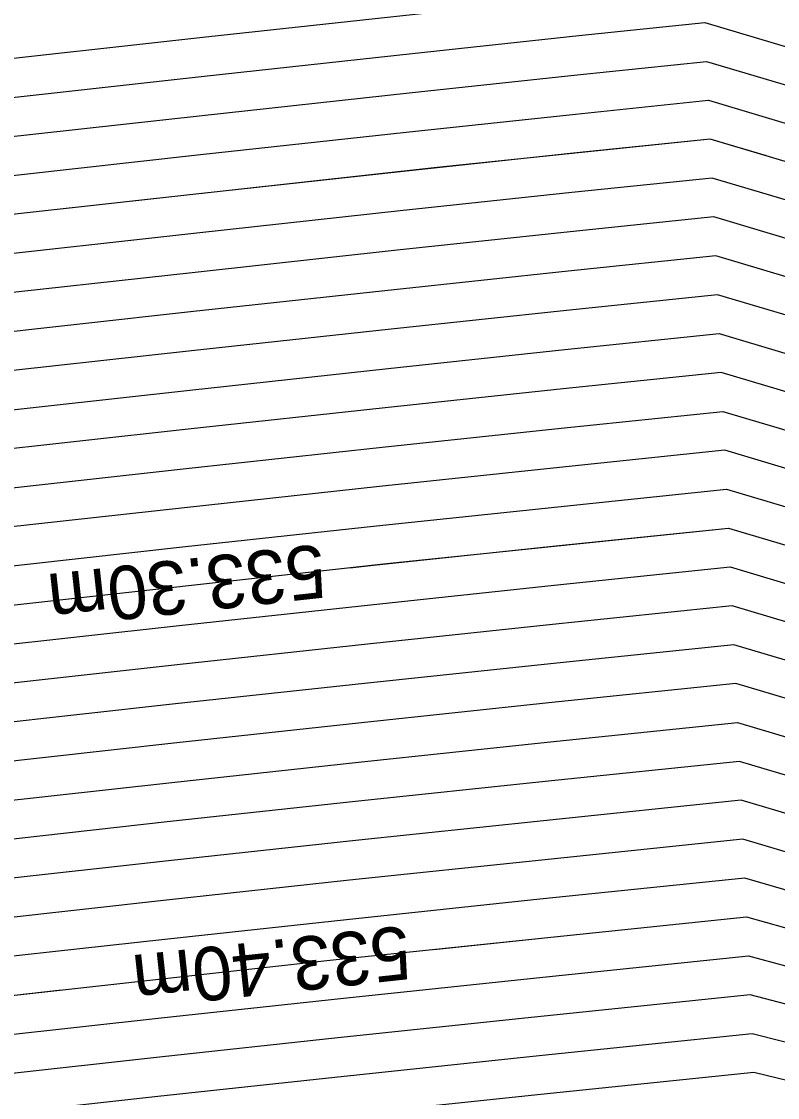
# Model space of a CAD drawing. Extents: x -866683 to -866410, y -1041951 to -1040252.
# Drawn here: x -866459.09 to -866454.85, y -1041936.13 to -1041930.1 of the extents above; entities that cross this region are included whole.
import ezdxf

# ---------------------------------------------------------------- set-up
doc = ezdxf.new("R2010")
doc.units = 0
doc.layers.add('V-VEDL', color=7, linetype='Continuous')
doc.layers.add('V_po_cm', color=7, linetype='Continuous')

msp = doc.modelspace()

# ---------------------------------------------------------------- linework, layer by layer
at = {"layer": 'V-VEDL'}
for points in [[(-866449.6778, -1041924.8534), (-866451.5122, -1041924.6245), (-866452.0867, -1041925.0785), (-866452.3185, -1041926.1012), (-866452.2076, -1041927.6924), (-866452.2736, -1041929.1497), (-866452.5165, -1041930.4732), (-866452.9364, -1041931.6628), (-866453.3395, -1041932.2146), (-866453.7258, -1041932.1285), (-866454.0953, -1041931.4045), (-866454.5968, -1041930.9482), (-866455.2304, -1041930.7597), (-866456.7616, -1041930.9181)], [(-866457.0626, -1041933.1405), (-866455.1284, -1041932.9404), (-866454.3281, -1041933.1785), (-866453.6946, -1041933.7549), (-866453.2278, -1041934.6694), (-866452.7398, -1041934.7782), (-866452.2307, -1041934.0812), (-866451.7003, -1041932.5785), (-866451.3935, -1041930.9067), (-866451.3101, -1041929.0659), (-866451.4503, -1041927.056), (-866451.3268, -1041925.7431), (-866450.9398, -1041925.1272), (-866449.6386, -1041925.2896)], [(-866456.7616, -1041930.9181), (-866459.4341, -1041931.2144), (-866460.3805, -1041931.3618), (-866460.937, -1041931.5083), (-866461.1038, -1041931.6539), (-866461.2514, -1041931.7484), (-866461.3799, -1041931.7917), (-866461.4892, -1041931.7839), (-866461.5612, -1041931.9236), (-866461.5959, -1041932.2109), (-866461.5932, -1041932.6457), (-866461.6511, -1041932.9421), (-866461.7696, -1041933.1), (-866461.9487, -1041933.1195), (-866462.3307, -1041933.2754), (-866462.9155, -1041933.5676), (-866463.7033, -1041933.9961), (-866464.3356, -1041934.0558), (-866464.8122, -1041933.7466), (-866465.4545, -1041932.3906)], [(-866461.3408, -1041933.8574), (-866461.0426, -1041933.8787), (-866460.8959, -1041933.8446), (-866460.7518, -1041933.7657), (-866460.6101, -1041933.6419), (-866460.1372, -1041933.5174), (-866459.3332, -1041933.3923), (-866457.0626, -1041933.1405)], [(-866457.3636, -1041935.3629), (-866455.0264, -1041935.1211), (-866454.0691, -1041935.3898), (-866453.3231, -1041936.048), (-866452.7882, -1041937.0959), (-866452.4298, -1041937.7979), (-866452.2476, -1041938.1541), (-866452.2361, -1041938.1747)], [(-866460.8845, -1041935.9529), (-866460.6391, -1041935.9705), (-866460.5184, -1041935.9424), (-866460.3998, -1041935.8774), (-866460.2832, -1041935.7756), (-866459.894, -1041935.6731), (-866459.2322, -1041935.5701), (-866457.3636, -1041935.3629)]]:
    msp.add_lwpolyline(points, dxfattribs=at)
at = {"layer": 'V_po_cm'}
for points in [[(-866461.657, -1041930.9468), (-866461.4999, -1041930.958), (-866461.3886, -1041930.9103), (-866461.2446, -1041930.8092), (-866461.0678, -1041930.6548), (-866460.4778, -1041930.4995), (-866459.4744, -1041930.3433), (-866458.0578, -1041930.1862), (-866456.8851, -1041930.0579), (-866455.9562, -1041929.9583), (-866455.2712, -1041929.8874), (-866454.7043, -1041930.0561)], [(-866461.6423, -1041931.1541), (-866461.4699, -1041931.1664), (-866461.3543, -1041931.1198), (-866461.2094, -1041931.0204), (-866461.0351, -1041930.8682), (-866460.4534, -1041930.7151), (-866459.4644, -1041930.5611), (-866458.0679, -1041930.4062), (-866456.9018, -1041930.2787), (-866455.9662, -1041930.1784), (-866455.261, -1041930.1055), (-866454.6775, -1041930.2791)], [(-866461.6277, -1041931.3614), (-866461.4399, -1041931.3749), (-866461.32, -1041931.3294), (-866461.1742, -1041931.2316), (-866461.0024, -1041931.0815), (-866460.4291, -1041930.9306), (-866459.4543, -1041930.7789), (-866458.0779, -1041930.6262), (-866456.9185, -1041930.4995), (-866455.9761, -1041930.3986), (-866455.2508, -1041930.3235), (-866454.6506, -1041930.5021)], [(-866461.6131, -1041931.5688), (-866461.4099, -1041931.5833), (-866461.2857, -1041931.5389), (-866461.139, -1041931.4427), (-866460.9697, -1041931.2949), (-866460.4048, -1041931.1462), (-866459.4442, -1041930.9967), (-866458.0879, -1041930.8463), (-866456.9352, -1041930.7203), (-866455.9861, -1041930.6187), (-866455.2406, -1041930.5416), (-866454.6237, -1041930.7252)], [(-866454.9157, -1041930.8533), (-866455.2304, -1041930.7597), (-866455.996, -1041930.8389), (-866456.9518, -1041930.9411), (-866458.0979, -1041931.0663), (-866459.0253, -1041931.1691)], [(-866454.57, -1041931.1712), (-866455.2202, -1041930.9777), (-866456.006, -1041931.059), (-866456.9685, -1041931.1619), (-866458.1079, -1041931.2863), (-866459.424, -1041931.4322), (-866460.3562, -1041931.5773), (-866460.9044, -1041931.7216), (-866461.0686, -1041931.8651), (-866461.2171, -1041931.9579), (-866461.3499, -1041932.0002), (-866461.5839, -1041931.9834)], [(-866454.5431, -1041931.3943), (-866455.21, -1041931.1958), (-866456.0159, -1041931.2792), (-866456.9852, -1041931.3827), (-866458.1179, -1041931.5063), (-866459.4139, -1041931.65), (-866460.3318, -1041931.7929), (-866460.8717, -1041931.935), (-866461.0334, -1041932.0763), (-866461.1828, -1041932.1675), (-866461.3199, -1041932.2086), (-866461.5693, -1041932.1907)], [(-866454.5162, -1041931.6173), (-866455.1998, -1041931.4139), (-866456.0259, -1041931.4993), (-866457.0019, -1041931.6035), (-866458.1279, -1041931.7263), (-866459.4038, -1041931.8678), (-866460.3075, -1041932.0085), (-866460.839, -1041932.1484), (-866460.9982, -1041932.2874), (-866461.1485, -1041932.377), (-866461.2898, -1041932.417), (-866461.5547, -1041932.3981)], [(-866454.4894, -1041931.8403), (-866455.1896, -1041931.632), (-866456.0358, -1041931.7195), (-866457.0186, -1041931.8243), (-866458.1379, -1041931.9463), (-866459.3937, -1041932.0856), (-866460.2832, -1041932.224), (-866460.8063, -1041932.3617), (-866460.963, -1041932.4986), (-866461.1142, -1041932.5865), (-866461.2598, -1041932.6255), (-866461.5401, -1041932.6054)], [(-866461.5255, -1041932.8127), (-866461.2298, -1041932.8339), (-866461.0799, -1041932.7961), (-866460.9278, -1041932.7098), (-866460.7736, -1041932.5751), (-866460.2589, -1041932.4396), (-866459.3836, -1041932.3034), (-866458.1479, -1041932.1663), (-866457.0353, -1041932.0451), (-866456.0458, -1041931.9397), (-866455.1794, -1041931.85), (-866454.4625, -1041932.0634)], [(-866454.4356, -1041932.2864), (-866455.1692, -1041932.0681), (-866456.0557, -1041932.1598), (-866457.0519, -1041932.2659), (-866458.1579, -1041932.3863), (-866459.3735, -1041932.5211), (-866460.2345, -1041932.6552), (-866460.7409, -1041932.7884), (-866460.8926, -1041932.921), (-866461.0456, -1041933.0056), (-866461.1998, -1041933.0423), (-866461.5108, -1041933.0201)], [(-866461.4776, -1041933.2287), (-866461.1636, -1041933.2512), (-866461.0092, -1041933.2153), (-866460.8574, -1041933.1321), (-866460.7082, -1041933.0018), (-866460.2102, -1041932.8707), (-866459.3634, -1041932.7389), (-866458.1679, -1041932.6063), (-866457.0686, -1041932.4867), (-866456.0657, -1041932.38), (-866455.159, -1041932.2862), (-866454.4087, -1041932.5094)], [(-866454.3819, -1041932.7325), (-866455.1488, -1041932.5042), (-866456.0756, -1041932.6001), (-866457.0853, -1041932.7075), (-866458.1779, -1041932.8264), (-866459.3533, -1041932.9567), (-866460.1859, -1041933.0863), (-866460.6755, -1041933.2152), (-866460.8222, -1041933.3433), (-866460.9715, -1041933.425), (-866461.1233, -1041933.4604), (-866461.432, -1041933.4383)], [(-866461.3864, -1041933.6478), (-866461.0829, -1041933.6696), (-866460.9337, -1041933.6348), (-866460.787, -1041933.5545), (-866460.6428, -1041933.4285), (-866460.1616, -1041933.3019), (-866459.3433, -1041933.1745), (-866458.1879, -1041933.0464), (-866457.102, -1041932.9283), (-866456.0856, -1041932.8203), (-866455.1386, -1041932.7223), (-866454.355, -1041932.9555)], [(-866457.2504, -1041933.1634), (-866457.1187, -1041933.1491), (-866456.0955, -1041933.0404), (-866455.1284, -1041932.9404), (-866454.3281, -1041933.1785), (-866453.7229, -1041933.7291)], [(-866461.2951, -1041934.0669), (-866461.0022, -1041934.0879), (-866460.8582, -1041934.0544), (-866460.7166, -1041933.9768), (-866460.5774, -1041933.8553), (-866460.1129, -1041933.733), (-866459.3231, -1041933.61), (-866458.2079, -1041933.4864), (-866457.1353, -1041933.3699), (-866456.1055, -1041933.2606), (-866455.1182, -1041933.1585), (-866454.3013, -1041933.4016)], [(-866454.2744, -1041933.6246), (-866455.108, -1041933.3765), (-866456.1154, -1041933.4807), (-866457.152, -1041933.5907), (-866458.2179, -1041933.7064), (-866459.313, -1041933.8278), (-866460.0886, -1041933.9486), (-866460.5447, -1041934.0686), (-866460.6814, -1041934.188), (-866460.8204, -1041934.2642), (-866460.9619, -1041934.2971), (-866461.2495, -1041934.2765)], [(-866454.2475, -1041933.8476), (-866455.0978, -1041933.5946), (-866456.1254, -1041933.7009), (-866457.1687, -1041933.8115), (-866458.2279, -1041933.9264), (-866459.3029, -1041934.0456), (-866460.0643, -1041934.1641), (-866460.512, -1041934.282), (-866460.6462, -1041934.3992), (-866460.7827, -1041934.4739), (-866460.9215, -1041934.5063), (-866461.2039, -1041934.486)], [(-866454.2206, -1041934.0707), (-866455.0876, -1041933.8127), (-866456.1353, -1041933.9211), (-866457.1854, -1041934.0323), (-866458.2379, -1041934.1464), (-866459.2928, -1041934.2634), (-866460.04, -1041934.3797), (-866460.4794, -1041934.4954), (-866460.611, -1041934.6104), (-866460.7449, -1041934.6837), (-866460.8812, -1041934.7154), (-866461.1583, -1041934.6956)], [(-866461.1126, -1041934.9051), (-866460.8408, -1041934.9246), (-866460.7072, -1041934.8935), (-866460.5758, -1041934.8215), (-866460.4467, -1041934.7087), (-866460.0156, -1041934.5953), (-866459.2827, -1041934.4812), (-866458.2479, -1041934.3664), (-866457.2021, -1041934.2531), (-866456.1453, -1041934.1412), (-866455.0774, -1041934.0307), (-866454.1938, -1041934.2937)], [(-866452.929, -1041936.1939), (-866453.4542, -1041935.1651), (-866454.1669, -1041934.5167), (-866455.0672, -1041934.2488), (-866456.1552, -1041934.3614), (-866457.2188, -1041934.4739), (-866458.2579, -1041934.5864), (-866459.2726, -1041934.699), (-866459.9913, -1041934.8108), (-866460.414, -1041934.9221), (-866460.5406, -1041935.0327), (-866460.6694, -1041935.1033), (-866460.8005, -1041935.1338), (-866461.067, -1041935.1147)], [(-866452.8792, -1041936.448), (-866453.4141, -1041935.4001), (-866454.14, -1041934.7397), (-866455.057, -1041934.4669), (-866456.1652, -1041934.5815), (-866457.2354, -1041934.6947), (-866458.2679, -1041934.8065), (-866459.2625, -1041934.9167), (-866459.967, -1041935.0264), (-866460.3813, -1041935.1355), (-866460.5054, -1041935.2439), (-866460.6317, -1041935.313), (-866460.7601, -1041935.3429), (-866461.0214, -1041935.3242)], [(-866452.8294, -1041936.7021), (-866453.374, -1041935.6352), (-866454.1131, -1041934.9628), (-866455.0468, -1041934.6849), (-866456.1751, -1041934.8017), (-866457.2521, -1041934.9155), (-866458.2779, -1041935.0265), (-866459.2524, -1041935.1345), (-866459.9427, -1041935.242), (-866460.3486, -1041935.3488), (-866460.4702, -1041935.4551), (-866460.5939, -1041935.5228), (-866460.7198, -1041935.5521), (-866460.9758, -1041935.5338)], [(-866452.2614, -1041937.9715), (-866453.346, -1041935.8467), (-866454.0903, -1041935.178), (-866455.0366, -1041934.903), (-866456.185, -1041935.0218), (-866457.2688, -1041935.1363), (-866458.2879, -1041935.2465), (-866459.2423, -1041935.3523), (-866459.9183, -1041935.4575), (-866460.3159, -1041935.5622), (-866460.435, -1041935.6662), (-866460.5562, -1041935.7326), (-866460.6795, -1041935.7613), (-866460.9301, -1041935.7433)], [(-866456.7789, -1041935.3036), (-866456.195, -1041935.242), (-866455.0264, -1041935.1211), (-866454.0691, -1041935.3898), (-866453.3231, -1041936.048), (-866453.1636, -1041936.3606)], [(-866460.8389, -1041936.1624), (-866460.5988, -1041936.1796), (-866460.4807, -1041936.1521), (-866460.3646, -1041936.0886), (-866460.2505, -1041935.9889), (-866459.8697, -1041935.8887), (-866459.2222, -1041935.7879), (-866458.3079, -1041935.6865), (-866457.3022, -1041935.5779), (-866456.2049, -1041935.4621), (-866455.0162, -1041935.3392), (-866454.048, -1041935.6016), (-866453.3002, -1041936.2494), (-866452.2454, -1041938.316)], [(-866460.8845, -1041935.9529), (-866460.6391, -1041935.9705), (-866460.5184, -1041935.9424), (-866460.3998, -1041935.8774), (-866460.2832, -1041935.7756), (-866459.894, -1041935.6731), (-866459.2322, -1041935.5701), (-866458.8667, -1041935.5296)], [(-866452.2374, -1041938.4882), (-866453.2773, -1041936.4508), (-866454.0268, -1041935.8134), (-866455.006, -1041935.5572), (-866456.2149, -1041935.6823), (-866457.3188, -1041935.7987), (-866458.3179, -1041935.9065), (-866459.2121, -1041936.0057), (-866459.8454, -1041936.1043), (-866460.2178, -1041936.2023), (-866460.3294, -1041936.2997), (-866460.4429, -1041936.3619), (-866460.5584, -1041936.3888), (-866460.7933, -1041936.372)], [(-866460.7476, -1041936.5815), (-866460.5181, -1041936.598), (-866460.4052, -1041936.5717), (-866460.2942, -1041936.5109), (-866460.1851, -1041936.4156), (-866459.821, -1041936.3198), (-866459.202, -1041936.2234), (-866458.3279, -1041936.1265), (-866457.3355, -1041936.0195), (-866456.2248, -1041935.9024), (-866454.9958, -1041935.7753), (-866454.0057, -1041936.0252), (-866453.2544, -1041936.6522), (-866452.2294, -1041938.6604)], [(-866452.2214, -1041938.8326), (-866453.2315, -1041936.8536), (-866453.9845, -1041936.237), (-866454.9856, -1041935.9934), (-866456.2348, -1041936.1226), (-866457.3522, -1041936.2403), (-866458.3379, -1041936.3465), (-866459.1919, -1041936.4412), (-866459.7967, -1041936.5354), (-866460.1524, -1041936.629), (-866460.259, -1041936.7221), (-866460.3674, -1041936.7815), (-866460.4777, -1041936.8072), (-866460.702, -1041936.7911)]]:
    msp.add_lwpolyline(points, dxfattribs=at)

# ---------------------------------------------------------------- texts
for s, rotation, p in [('533.30m', 186.27623, (-866457.405, -1041933.0295)), ('533.40m', 186.17616, (-866456.9292, -1041935.169))]:
    msp.add_text(s, height=0.3, rotation=rotation, dxfattribs=at).set_placement(p)

doc.saveas('drawing.dxf')
